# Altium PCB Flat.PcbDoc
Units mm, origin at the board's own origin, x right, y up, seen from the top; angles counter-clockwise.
Board outline 90.12 x 95.76 mm, 4 copper layers (Top Layer-B, Layer 1 -A, Layer 2 -C, Bottom Layer -D), stack 0.603 mm thick; 3 components, 16 nets, 161 pads, 10 vias.
Unrouted connection lines stored in the file: 4.
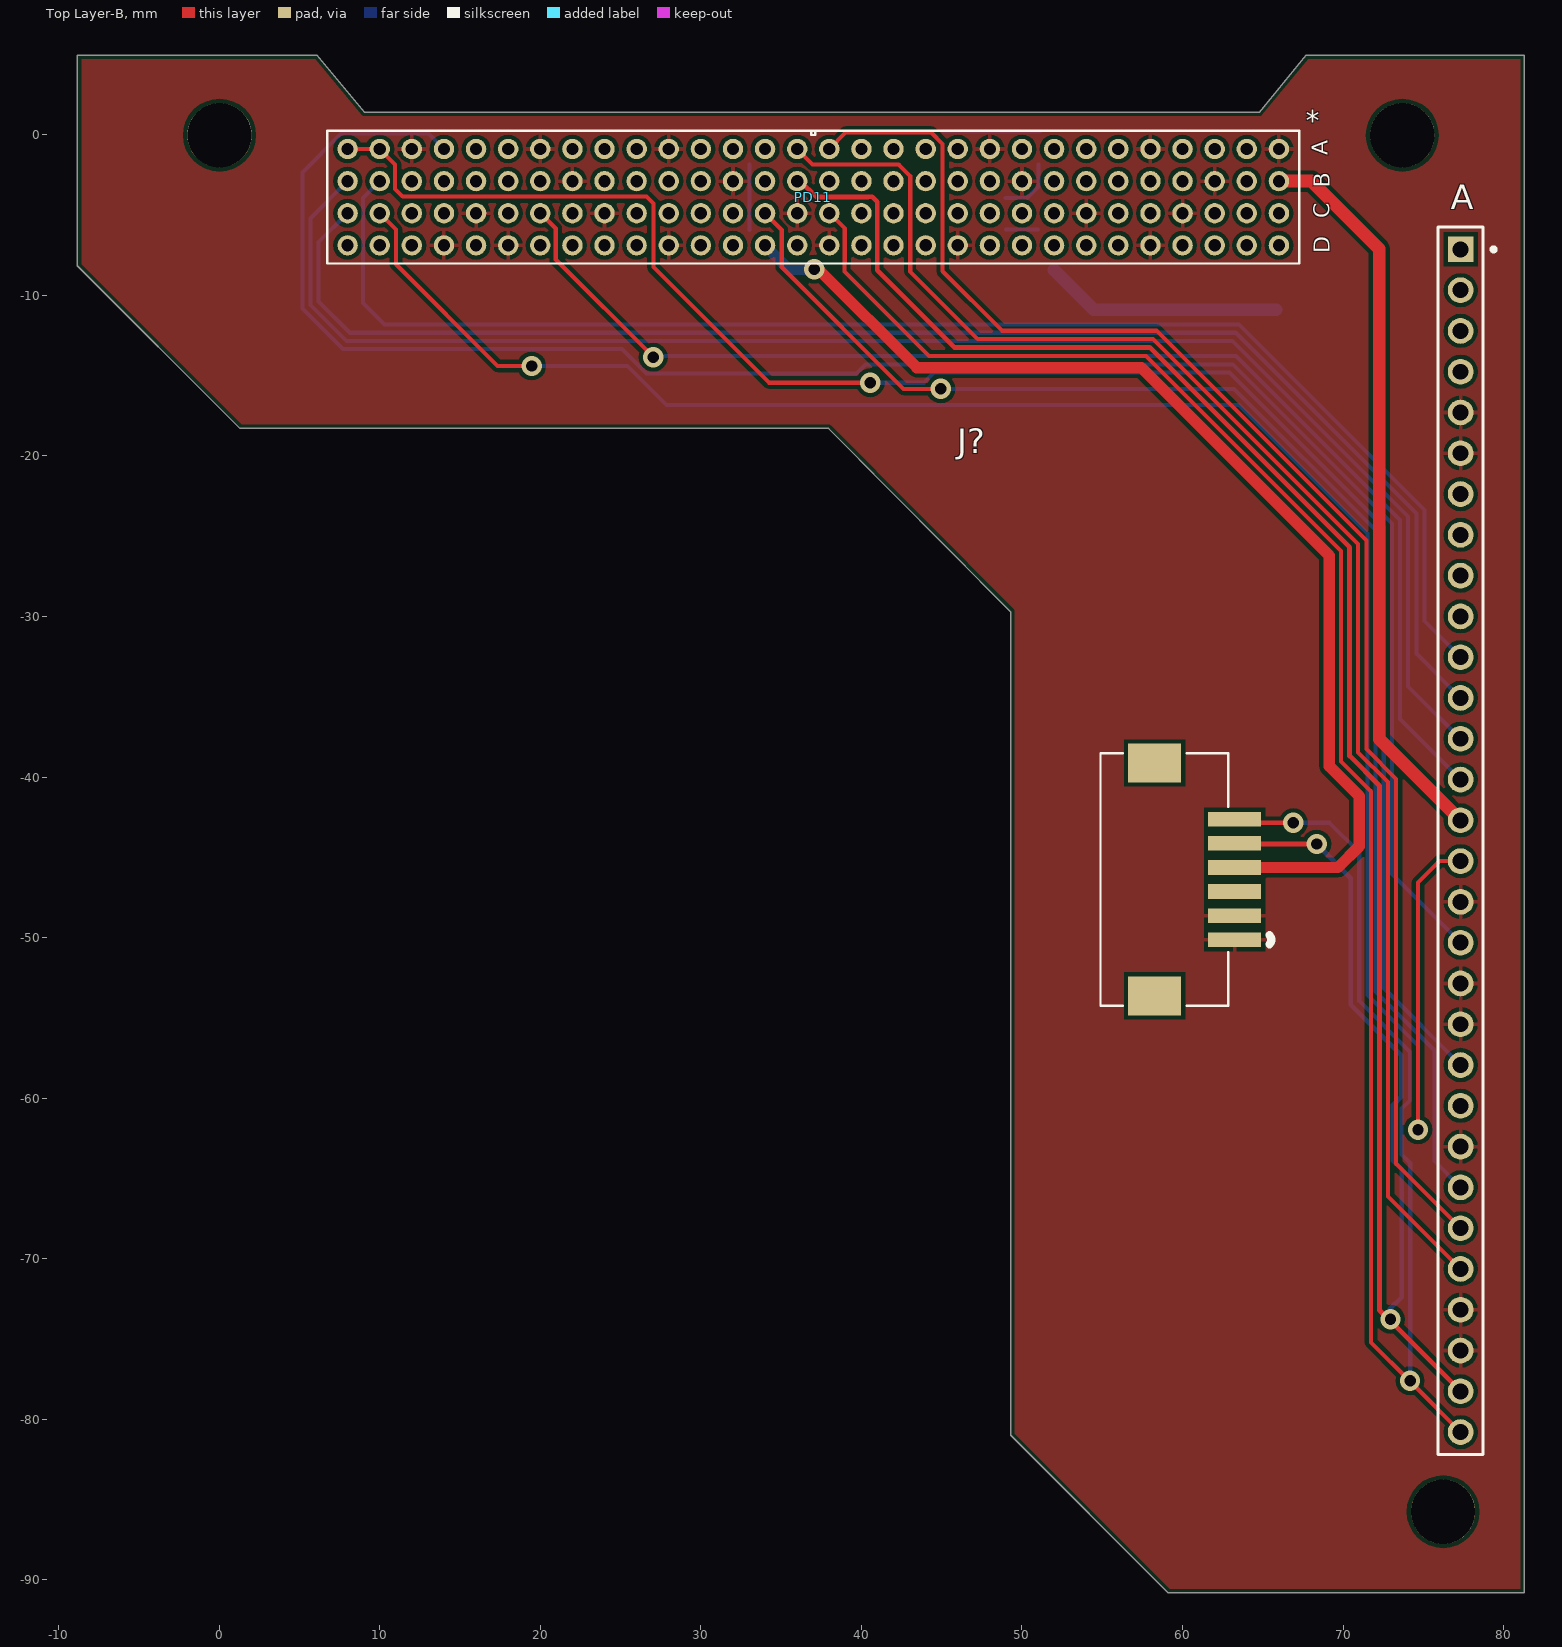
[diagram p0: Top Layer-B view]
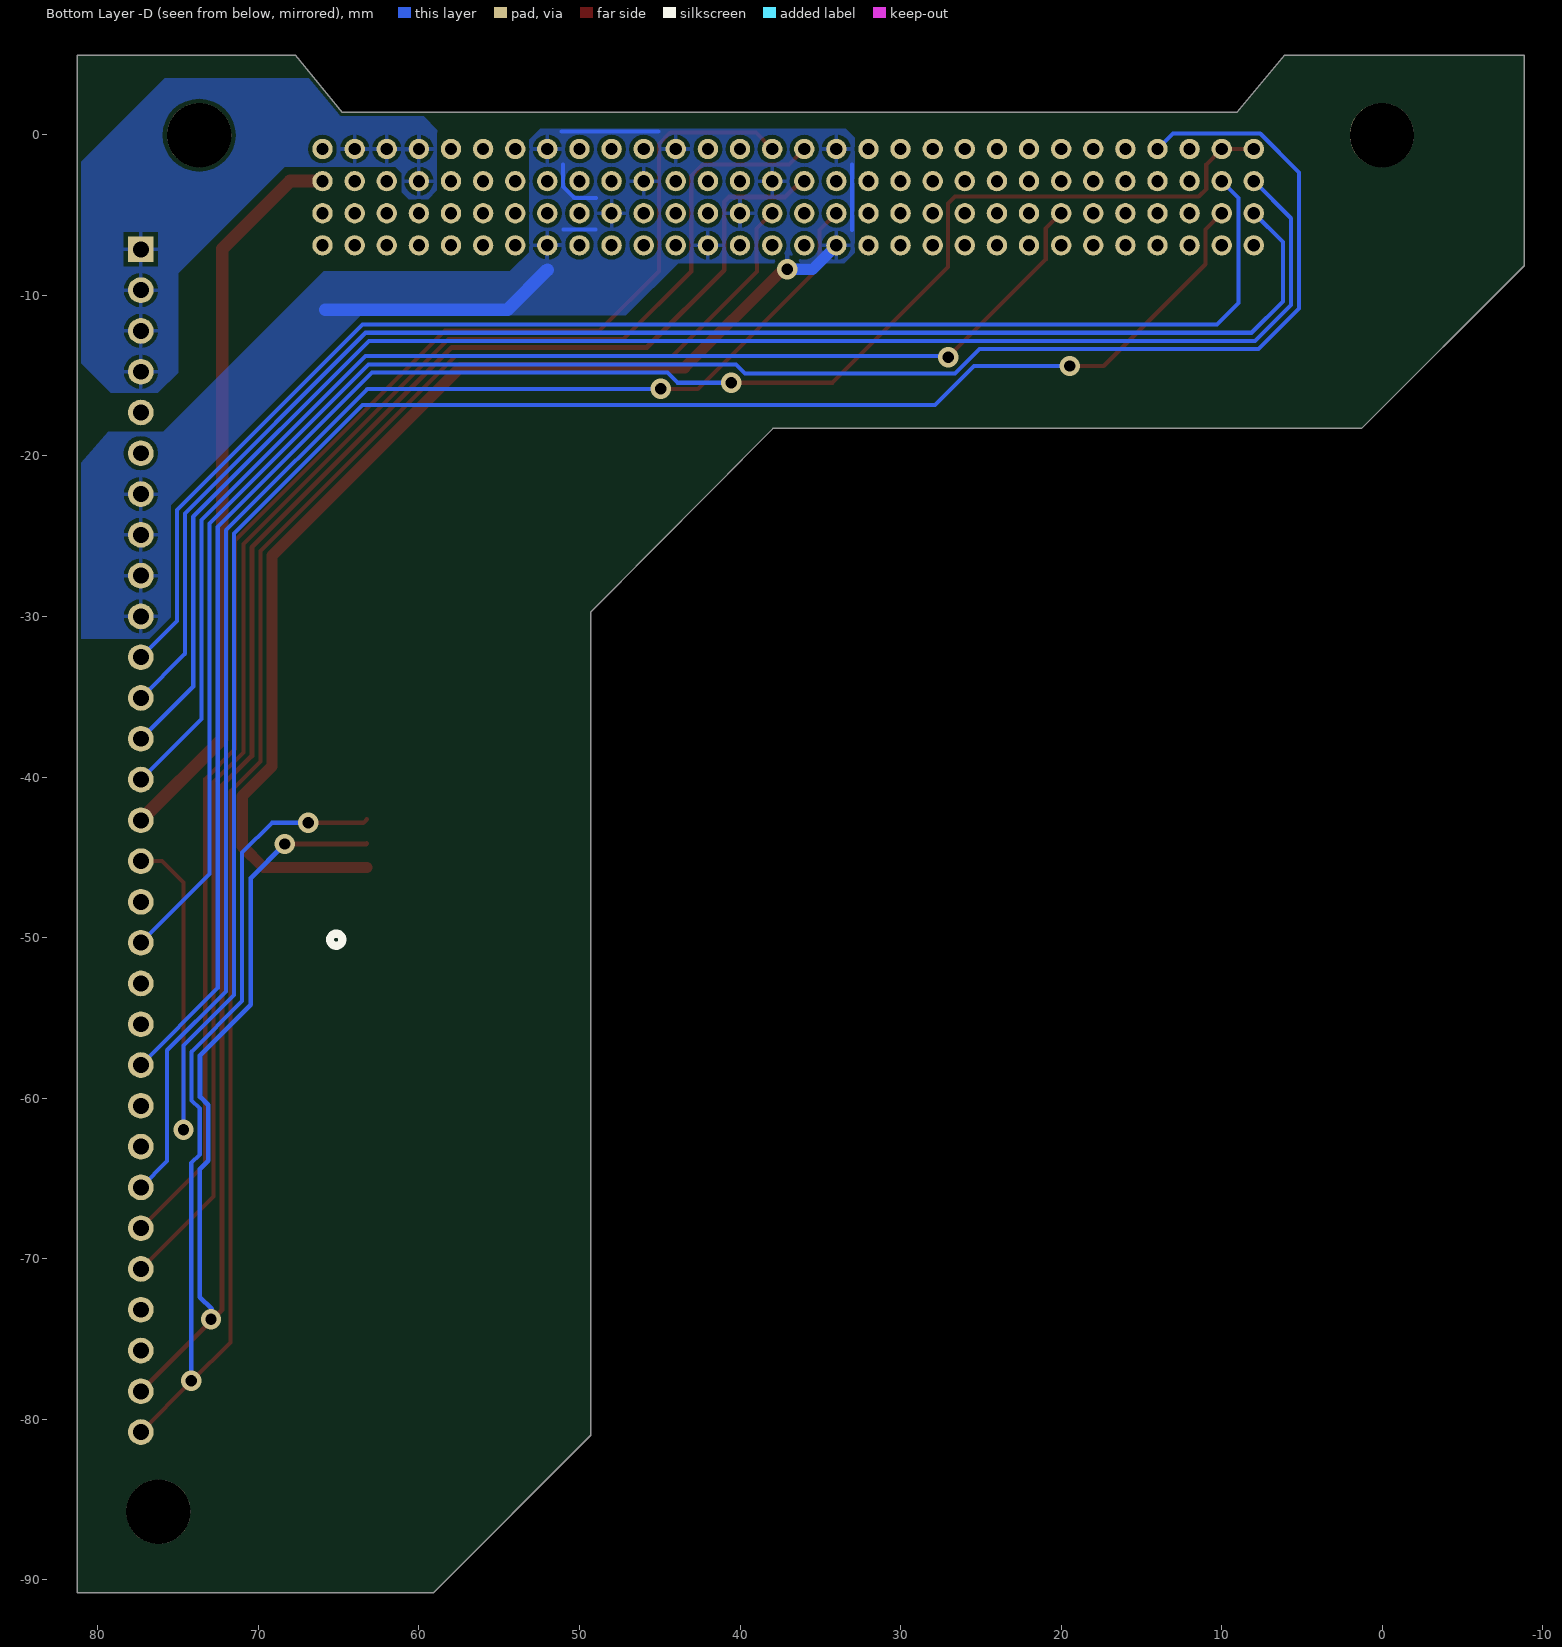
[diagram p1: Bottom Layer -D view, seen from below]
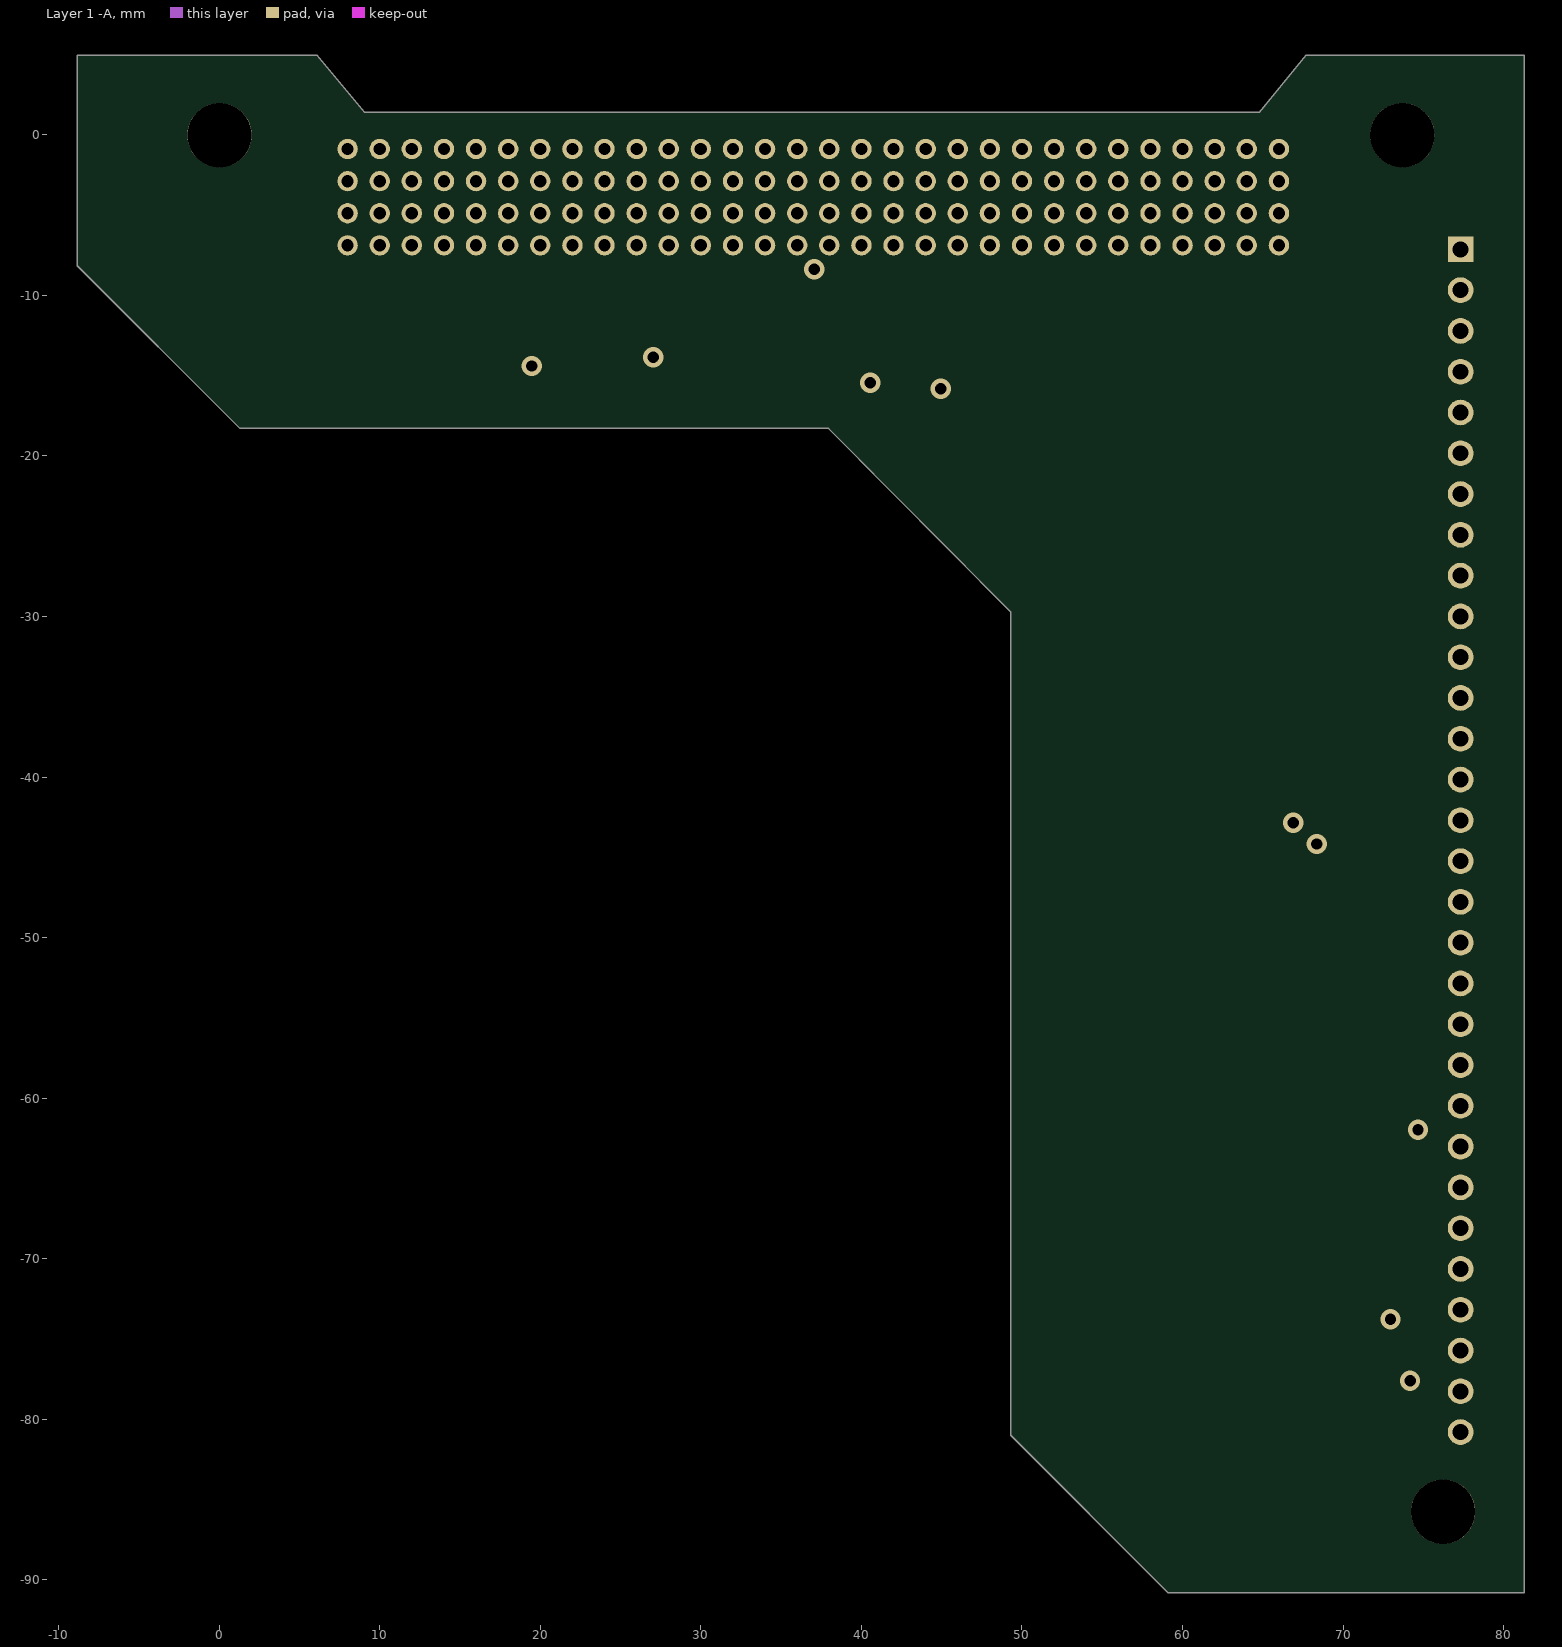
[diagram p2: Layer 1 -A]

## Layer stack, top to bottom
Top Solder: solder mask 0.0102, Solder Resist, Dk 3.5
Top Layer-B: signal copper 0.0356
Dielectric 2: prepreg 0.0711, PP-006, Dk 4.1
Layer 1 -A: signal copper 0.035
Dielectric 1: dielectric 0.32, FR-4, Dk 4.8
Layer 2 -C: signal copper 0.035
Dielectric 3: prepreg 0.0711, PP-006, Dk 4.1
Bottom Layer -D: signal copper 0.0356
Bottom Solder: solder mask 0.0102, Solder Resist, Dk 3.5

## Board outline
1.295,-18.288 -8.839,-8.153 -8.839,4.953 6.096,4.953 9.055,1.397 64.77,1.397 67.691,4.953 81.28,4.953 81.28,-90.805 59.08,-90.805 59.08,-90.78 49.301,-81.001 49.301,-29.714 37.951,-18.288

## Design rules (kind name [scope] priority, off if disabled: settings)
BoardOutlineClearance [All] p1: gap=0.254 ignorepadtopadclearanceinfootprint=FALSE except(0: Arc-SplitContinuation Track-SplitContinuation SMDPad-SplitContinuation THPad-SplitContinuation Via-SplitContinuation Fill-SplitContinuation Poly-SplitContinuation Region-SplitContinuation Text-SplitContinuation)
Clearance [All] p1: gap=0.254 ignorepadtopadclearanceinfootprint=FALSE except(0: Arc-Hole Track-Hole SMDPad-Hole THPad-Hole Via-Hole Fill-Hole Poly-Hole Region-Hole Text-Hole; 0.2: Arc-SMDPad Arc-THPad Track-SMDPad Track-THPad)
PolygonConnect [All] p1: connectstyle=Relief reliefconductorwidth=0.254 reliefentries=4 polygonreliefangle="90 Angle" airgapwidth=0.254
RoutingVias [All] p1: holewidth=0.711 width=1.27 viastyle="Through Hole" minholewidth=0.711 minwidth=1.27 maxholewidth=0.711 maxwidth=1.27
SolderMaskExpansion [All] p1: expansion=0.102
Width "Width- RBF" [InNet('NetB_1')] p1: maxlimit=1 minlimit=0.254 preferedwidth=0.254 minimp=50.000000 maximp=50.000000 favimp=50.000000
Width [All] p2: maxlimit=1 minlimit=0.254 preferedwidth=0.254 minimp=50.000000 maximp=50.000000 favimp=50.000000
Width Width_bat-heater [InNet('NetD_16')] p3: maxlimit=1 minlimit=0.254 preferedwidth=0.8 toplayer_minwidth=0.8 midlayer1_prefwidth=0.254 midlayer2_prefwidth=0.254 bottomlayer_minwidth=0.8 minimp=50.000000 maximp=50.000000 favimp=50.000000
Width Width_12v [InNet('NetA_29')] p4: maxlimit=1 minlimit=0.254 preferedwidth=0.254 minimp=50.000000 maximp=50.000000 favimp=50.000000
Width Width_3v2 [All] p5: maxlimit=1 minlimit=0.254 preferedwidth=0.8 toplayer_minwidth=0.8 midlayer1_prefwidth=0.254 midlayer2_prefwidth=0.254 bottomlayer_minwidth=0.8 minimp=50.000000 maximp=50.000000 favimp=50.000000
Width Width_B+ [InNet('NetA_2')] p6: maxlimit=1 minlimit=0.254 preferedwidth=0.8 toplayer_minwidth=0.8 midlayer1_prefwidth=0.254 midlayer2_prefwidth=0.254 bottomlayer_minwidth=0.8 minimp=50.000000 maximp=50.000000 favimp=50.000000
30 further rules are at their usual default settings.

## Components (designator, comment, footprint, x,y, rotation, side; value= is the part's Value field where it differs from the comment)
A "Header 30" HDR1X30 77.318,-7.137 r270 top
J? "292227-6" CON6_1X6_DRH_HPI125_TYC 63.246,-50.131 r90 top
PD11 "1375799-1" CONN_1375799-1_T 66.001,-6.889 r180 top locked

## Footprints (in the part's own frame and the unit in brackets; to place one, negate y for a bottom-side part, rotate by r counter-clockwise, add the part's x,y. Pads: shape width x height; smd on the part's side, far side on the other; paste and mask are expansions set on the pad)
CON6_1X6_DRH_HPI125_TYC [mil]
  rect 36x130 smd: 1(0,0) 2(59.06,0) 3(118.11,0) 4(177.17,0) 5(236.22,0) 6(295.28,0)
  rect 95x130 smd: 7(-137.86,196) 8(433.14,196)
  silkscreen extent -162,-90 458,329, body extent 0,0 10,10, height 10
CONN_1375799-1_T [mil]
  round 50 hole 30 mask+0: 1(0,-236.22) 2(78.74,-236.22) 3(157.48,-236.22) 4(236.22,-236.22) 5(314.96,-236.22) 6(393.7,-236.22) 7(472.44,-236.22) 8(551.18,-236.22) 9(629.92,-236.22) 10(708.66,-236.22) 11(787.4,-236.22) 12(866.14,-236.22) 13(944.88,-236.22) 14(1023.62,-236.22) 15(1102.36,-236.22) 16(1181.1,-236.22) 17(1259.84,-236.22) 18(1338.58,-236.22) 19(1417.32,-236.22) 20(1496.06,-236.22) 21(1574.8,-236.22) 22(1653.54,-236.22) 23(1732.28,-236.22) 24(1811.02,-236.22) 25(1889.76,-236.22) 26(1968.5,-236.22) 27(2047.24,-236.22) 28(2125.98,-236.22) 29(2204.72,-236.22) 30(2283.46,-236.22) 31(0,-157.48) 32(78.74,-157.48) 33(157.48,-157.48) 34(236.22,-157.48) 35(314.96,-157.48) 36(393.7,-157.48) 37(472.44,-157.48) 38(551.18,-157.48) 39(629.92,-157.48) 40(708.66,-157.48) 41(787.4,-157.48) 42(866.14,-157.48) 43(944.88,-157.48) 44(1023.62,-157.48) 45(1102.36,-157.48) 46(1181.1,-157.48) 47(1259.84,-157.48) 48(1338.58,-157.48) 49(1417.32,-157.48) 50(1496.06,-157.48) 51(1574.8,-157.48) 52(1653.54,-157.48) 53(1732.28,-157.48) 54(1811.02,-157.48) 55(1889.76,-157.48) 56(1968.5,-157.48) 57(2047.24,-157.48) 58(2125.98,-157.48) 59(2204.72,-157.48) 60(2283.46,-157.48) 61(0,-78.74) 62(78.74,-78.74) 63(157.48,-78.74) 64(236.22,-78.74) 65(314.96,-78.74) 66(393.7,-78.74) 67(472.44,-78.74) 68(551.18,-78.74) 69(629.92,-78.74) 70(708.66,-78.74) 71(787.4,-78.74) 72(866.14,-78.74) 73(944.88,-78.74) 74(1023.62,-78.74) 75(1102.36,-78.74) 76(1181.1,-78.74) 77(1259.84,-78.74) 78(1338.58,-78.74) 79(1417.32,-78.74) 80(1496.06,-78.74) 81(1574.8,-78.74) 82(1653.54,-78.74) 83(1732.28,-78.74) 84(1811.02,-78.74) 85(1889.76,-78.74) 86(1968.5,-78.74) 87(2047.24,-78.74) 88(2125.98,-78.74) 89(2204.72,-78.74) 90(2283.46,-78.74) 91(0,0) 92(78.74,0) 93(157.48,0) 94(236.22,0) 95(314.96,0) 96(393.7,0) 97(472.44,0) 98(551.18,0) 99(629.92,0) 100(708.66,0) 101(787.4,0) 102(866.14,0) 103(944.88,0) 104(1023.62,0) 105(1102.36,0) 106(1181.1,0) 107(1259.84,0) 108(1338.58,0) 109(1417.32,0) 110(1496.06,0) 111(1574.8,0) 112(1653.54,0) 113(1732.28,0) 114(1811.02,0) 115(1889.76,0) 116(1968.5,0) 117(2047.24,0) 118(2125.98,0) 119(2204.72,0) 120(2283.46,0)
  silkscreen extent -50,-281 2334,44, body extent -45,-341 2329,54, height 368
HDR1X30 [mm] "Connector; Header; 30 Position"
  rect 1.6x1.6 hole 0.99: 1(0,0)
  round 1.6 hole 0.99: 2(2.54,0) 3(5.08,0) 4(7.62,0) 5(10.16,0) 6(12.7,0) 7(15.24,0) 8(17.78,0) 9(20.32,0) 10(22.86,0) 11(25.4,0) 12(27.94,0) 13(30.48,0) 14(33.02,0) 15(35.56,0) 16(38.1,0) 17(40.64,0) 18(43.18,0) 19(45.72,0) 20(48.26,0) 21(50.8,0) 22(53.34,0) 23(55.88,0) 24(58.42,0) 25(60.96,0) 26(63.5,0) 27(66.04,0) 28(68.58,0) 29(71.12,0) 30(73.66,0)
  silkscreen extent -1.4,-1.4 75.06,2.18

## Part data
A: "Header, 30-Pin"
J? PD11: "No Description Available"

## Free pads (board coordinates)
  round 4 hole 4: 1(0.027,-0.027) 1(73.687,-0.027) 1(76.227,-85.757)

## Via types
v1: diameter 1.27, hole 0.711, Top Layer-B to Bottom Layer -D, 10 vias

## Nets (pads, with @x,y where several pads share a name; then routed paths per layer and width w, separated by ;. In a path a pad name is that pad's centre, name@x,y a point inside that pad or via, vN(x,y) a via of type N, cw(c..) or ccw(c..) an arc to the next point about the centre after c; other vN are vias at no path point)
NetA_1: A.1 A.2 A.3 A.4 PD11.2 PD11.3 PD11.4 PD11.34 | length 0
NetA_5: A.5 A.6 A.17 A.19 A.20 A.23 A.27 A.28 J?.1 J?.2 PD11.1 PD11.5 PD11.10 PD11.14 PD11.20 PD11.24 PD11.28 PD11.33 PD11.39 PD11.43 PD11.48 PD11.53 PD11.64 PD11.67 PD11.72 PD11.76 PD11.82 PD11.86 PD11.95 PD11.101 PD11.105 PD11.110 PD11.115 PD11.117 | length 0.2
  Layer 1 -A w0.254: A.23@77.054,-62.589 A.23@77.114,-62.649 ; A.19@77.054,-52.429 A.19@77.114,-52.489
NetA_7: A.7 A.8 A.9 A.10 J?.4 PD11.8 PD11.12 PD11.17 PD11.41 PD11.45 PD11.70 PD11.74 PD11.98 PD11.103 PD11.107 | length 101.2
  Top Layer-B w0.254: PD11.17@33.998,-0.889 PD11.17
  Top Layer-B w0.7: v1(37.059,-8.382) 37.325,-8.382 43.449,-14.506 57.427,-14.506 69.142,-26.222 69.142,-39.33 71.003,-41.191 71.003,-44.31 69.683,-45.631 J?.4
  Bottom Layer -D w0.254: 33.033,-5.921 33.033,-1.857 ; 45.093,0.203 51.105,0.203 ; 48.963,-3.927 50.323,-3.927 51.039,-3.211 51.039,-1.851 ; 49.001,-5.889 51.001,-5.889 ; PD11.8 PD11.8@52.001,-0.693
  Bottom Layer -D w0.7: PD11.107 35.494,-8.382 v1(37.059,-8.382)
  Bottom Layer -D w0.8: 52.001,-8.415 54.483,-10.897 65.837,-10.897
NetA_11: A.11 PD11.59 | length 89.6
  Bottom Layer -D w0.254: PD11.59 8.963,-3.927 8.963,-10.487 10.3,-11.824 63.525,-11.824 75.07,-23.368 75.07,-30.289 A.11
NetA_12: A.12 PD11.90 | length 92.7
  Bottom Layer -D w0.254: PD11.90 6.198,-6.692 6.198,-10.389 8.141,-12.332 63.315,-12.332 74.562,-23.578 74.562,-32.321 A.12
NetA_13: A.13 PD11.60 | length 97.7
  Bottom Layer -D w0.254: PD11.60 5.69,-5.2 5.69,-10.599 7.93,-12.84 63.105,-12.84 74.054,-23.789 74.054,-34.353 A.13
NetA_14: A.14 PD11.84 | length 80.4
  Top Layer-B w0.254: PD11.84 20.963,-5.851 20.963,-7.78 v1(27.038,-13.856)
  Bottom Layer -D w0.254: v1(27.038,-13.856) 27.102,-13.792 63.339,-13.792 73.546,-23.999 73.546,-36.385 A.14
NetA_15: A.15 PD11.31 | length 45.7
  Top Layer-B w0.8: PD11.31 68.027,-2.889 72.25,-7.112 72.25,-37.63 A.15
NetA_16: A.16 PD11.89 | length 128.1
  Top Layer-B w0.254: PD11.89 11.011,-5.899 11.011,-8.064 17.348,-14.402 v1(19.456,-14.402) ; v1(74.663,-61.963) 74.663,-46.581 76.007,-45.237 A.16
  Bottom Layer -D w0.254: v1(19.456,-14.402) 25.429,-14.402 27.868,-16.84 63.513,-16.84 71.514,-24.841 71.514,-53.57 74.663,-56.72 v1(74.663,-61.963)
NetA_18: A.18 PD11.27 | length 120.5
  Layer 1 -A w0.254: A.18@77.054,-49.889 A.18@77.114,-49.949
  Bottom Layer -D w0.254: PD11.27 13.039,0.073 7.603,0.073 5.182,-2.348 5.182,-10.809 7.72,-13.348 25.093,-13.348 26.617,-14.872 39.686,-14.872 40.257,-14.3 63.128,-14.3 73.038,-24.21 73.038,-46.037 A.18
NetA_21: A.21 A.22 PD11.29 PD11.30 | length 113.7
  Top Layer-B w0.254: PD11.30 PD11.29 10.963,-1.851 10.963,-3.381 11.433,-3.851 26.609,-3.851 27.039,-4.281 27.039,-8.243 34.239,-15.443 v1(40.551,-15.443)
  Layer 1 -A w0.254: A.22@77.054,-60.049 A.22@77.114,-60.109 ; A.21@77.054,-57.509 A.21@77.114,-57.569
  Bottom Layer -D w0.254: v1(40.551,-15.443) 43.889,-15.443 44.524,-14.808 62.918,-14.808 72.53,-24.42 72.53,-53.149 A.21
NetA_24: A.24 PD11.77 | length 90.7
  Top Layer-B w0.254: PD11.77 35.039,-5.927 35.039,-8.231 42.632,-15.824 v1(44.945,-15.824)
  Bottom Layer -D w0.254: v1(44.945,-15.824) 63.215,-15.824 72.022,-24.631 72.022,-53.36 75.679,-57.018 75.679,-63.919 A.24
NetA_25: A.25 PD11.15 | length 94.4
  Top Layer-B w0.254: PD11.15 39.017,0.127 44.348,0.127 45.039,-0.564 45.039,-8.501 48.743,-12.205 58.38,-12.205 71.443,-25.268 71.443,-38.251 73.304,-40.112 73.304,-64.084 A.25
  Layer 1 -A w0.254: A.25@77.054,-67.669 A.25@77.114,-67.729
NetA_26: A.26 PD11.16 | length 96.5
  Top Layer-B w0.254: PD11.16 36.963,-1.851 42.323,-1.851 43.039,-2.567 43.039,-8.508 47.244,-12.713 58.169,-12.713 70.935,-25.479 70.935,-38.462 72.796,-40.322 72.796,-66.116 A.26
  Layer 1 -A w0.254: A.26@77.054,-70.209 A.26@77.114,-70.269
NetA_29: A.29 J?.5 PD11.46 | length 139.4
  Top Layer-B w0.3: PD11.46 36.198,-2.889 37.183,-3.874 40.409,-3.874 40.418,-3.865 40.678,-3.865 40.986,-4.173 40.986,-8.436 45.794,-13.244 57.949,-13.244 70.404,-25.699 70.404,-38.682 72.265,-40.542 72.265,-73.205 72.892,-73.831 A.29 ; J?.5 63.285,-44.171 v1(68.351,-44.171)
  Bottom Layer -D w0.3: v1(68.351,-44.171) 70.475,-46.294 70.475,-54.182 73.624,-57.332 73.624,-59.919 73.116,-60.427 73.116,-63.888 73.65,-64.422 73.65,-72.388 72.911,-73.127 72.911,-73.736 v1(72.949,-73.774)
NetA_30: A.30 J?.6 PD11.75 | length 143.4
  Top Layer-B w0.254: PD11.75 38.963,-5.851 38.963,-7.951 38.951,-7.963 38.951,-8.522 44.204,-13.775 57.729,-13.775 69.873,-25.919 69.873,-39.027 71.734,-40.888 71.734,-75.214 74.149,-77.629 A.30 ; J?.6 63.465,-42.85 v1(66.904,-42.85)
  Bottom Layer -D w0.254: v1(66.904,-42.85) 69.151,-42.85 71.006,-44.704 71.006,-53.962 74.155,-57.112 74.155,-60.139 73.647,-60.647 73.647,-63.513 74.181,-64.046 74.181,-77.597 v1(74.168,-77.61)
pads on no net: J?.3 J?.7 J?.8 PD11.6 PD11.7 PD11.9 PD11.11 PD11.13 PD11.18 PD11.19 PD11.21 PD11.22 PD11.23 PD11.25 PD11.26 PD11.32 PD11.35 PD11.36 PD11.37 PD11.38 PD11.40 PD11.42 PD11.44 PD11.47 PD11.49 PD11.50 PD11.51 PD11.52 PD11.54 PD11.55 PD11.56 PD11.57 PD11.58 PD11.61 PD11.62 PD11.63 PD11.65 PD11.66 PD11.68 PD11.69 PD11.71 PD11.73 PD11.78 PD11.79 PD11.80 PD11.81 PD11.83 PD11.85 PD11.87 PD11.88 PD11.91 PD11.92 PD11.93 PD11.94 PD11.96 PD11.97 PD11.99 PD11.100 PD11.102 PD11.104 PD11.106 PD11.108 PD11.109 PD11.111 PD11.112 PD11.113 PD11.114 PD11.116 PD11.118 PD11.119 PD11.120
copper on no net: | length 0
  Bottom Layer -D w0.254: 9.97,-6.92 10.001,-6.889

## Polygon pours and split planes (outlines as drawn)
no net on Board outline "Board outline-No Net" (solid, shelved): -5.817,-26.137
NetA_5 on Top Layer-B "Top Layer-B-NetA_5" (solid, pour order 26): -8.547,5.448 81.89,5.448 81.89,-91.643 80.747,-92.786 80.175,-92.215 54.775,-92.215 54.775,-91.211 -8.547,-27.889
no net on Top Layer-B "Top Layer-B-No Net" (solid, pour order 6): 61.227,-0.127
no net on Top Layer-B "Top Layer-B-No Net 1" (solid, pour order 4): 61.227,-0.127
NetA_7 on Bottom Layer -D "Bottom Layer -D-NetA_7" (solid, pour order 16): 33.414,0.368 34.29,0.368 52.451,0.368 53.124,-0.305 53.124,-7.302 52.426,-8.001 33.503,-8.001 32.855,-7.353 32.855,-0.191
NetA_7 on Bottom Layer -D "Bottom Layer -D-NetA_7 1" (solid, pour order 34): 81.826,-31.382 81.826,-21.361 79.335,-18.491 75.908,-18.491 65.926,-8.509 54.331,-8.509 52.479,-6.657 43.367,-6.657 43.367,-7.502 47.104,-11.239 63.627,-11.239 75.463,-23.076 75.463,-30.061 76.784,-31.382
NetA_1 on Bottom Layer -D "Bottom Layer -D-NetA_1" (solid, pour order 32): 61.481,-2.007 68.364,-2.007 74.981,-8.623 74.981,-14.808 76.251,-16.078 79.184,-16.078 81.775,-13.487 81.775,-2.438 75.819,3.518 62.09,3.518 58.8,0.227
no net on Bottom Layer -D "Bottom Layer -D-No Net" (solid, pour order 20): 34.169,0.248
no net on Bottom Layer -D "Bottom Layer -D-No Net 1" (solid, pour order 18): 34.169,0.248
NetA_1 on Bottom Layer -D "Bottom Layer -D-NetA_1 1" (solid, pour order 10): 63.919,0.229 58.877,0.229 58.877,-3.467 59.423,-4.013 60.63,-4.013 61.074,-3.569 61.074,-2.375 61.112,-2.375 61.481,-2.007 64.541,-2.007 65.126,-1.422 65.126,-0.313 64.554,0.241
no net on Bottom Layer -D "Bottom Layer -D-No Net 2" (solid, pour order 8): 61.062,-1.689
no net on Layer 1 -A "Layer 1 -A-No Net" (solid, pour order 30): 76.009,-15.9

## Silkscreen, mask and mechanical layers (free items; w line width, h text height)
Mechanical 1:
  lines w0.1: 6.22,-3.175 6.22,-0.762 ; 6.35,0.713 7.112,0.713
Board outline:
  lines w0.2: -8.839,-8.153 -8.839,4.953 6.096,4.953 9.055,1.397 64.77,1.397 67.691,4.953 81.28,4.953 81.28,-90.805 59.08,-90.805 49.301,-81.026 49.301,-29.714 37.951,-18.288 1.295,-18.288 -8.839,-8.153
